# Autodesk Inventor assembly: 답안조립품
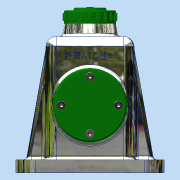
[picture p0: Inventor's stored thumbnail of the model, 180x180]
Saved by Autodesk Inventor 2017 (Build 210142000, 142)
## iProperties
Part Number: 답안조립품
Material: 일반
Document SubType Name: Assembly
Designer: MRC
Author: MRC
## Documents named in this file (14)
- C:\Users\MRC\Desktop\700907V1006\답안조립품.iam
- C:\Users\MRC\Desktop\700907V1006\본체.ipt
- C:\Users\MRC\Desktop\700907V1006\Ű 5 x 5 x 14.ipt
- C:\Users\MRC\Desktop\700907V1006\V-벨트풀리.ipt
- C:\Users\MRC\Desktop\700907V1006\뒤커버.ipt
- C:\Users\MRC\Desktop\700907V1006\멈춤링 15 x 1.ipt
- C:\Users\MRC\Desktop\700907V1006\베어링 15 x 35 x 11.ipt
- C:\Users\MRC\Desktop\700907V1006\볼트 M4 x 10.ipt
- C:\Users\MRC\Desktop\700907V1006\볼트 M6 x 12.ipt
- C:\Users\MRC\Desktop\700907V1006\상부캡.ipt
- C:\Users\MRC\Desktop\700907V1006\앞커버.ipt
- C:\Users\MRC\Desktop\700907V1006\오일실 15 25 7.ipt
- C:\Users\MRC\Desktop\700907V1006\와셔.ipt
- C:\Users\MRC\Desktop\700907V1006\축.ipt
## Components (2 placed, 2 different names)
1. Ű 5 x 5 x 14:1
2. V-벨트풀리:1 — 플러쉬:1
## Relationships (1: Flush 1)
- 플러쉬:1 [Flush]: V-벨트풀리:1
